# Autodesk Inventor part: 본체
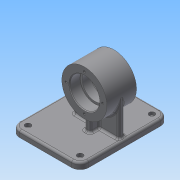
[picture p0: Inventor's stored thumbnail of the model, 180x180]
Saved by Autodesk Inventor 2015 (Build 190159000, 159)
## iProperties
Created: 2019-09
Part Number: 본체
Material: 일반
Document SubType Name: Modeling
Designer: user
Density: 1 g/cm^3
Appearance: 기본값
Author: user
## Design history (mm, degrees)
sketch "스케치1"
  geometry: C1 r 32 at (0, 0); 1 further point
  constraints: 1 centre point, 1 coincident
  dimensions: "d0" = 64 diameter of C1
extrude "돌출1" new body sketch "스케치1" stored distance "d1" = 42; taper "d2" = 0 deg
sketch "스케치2"
  geometry: L1 (32, -21)-(-32, -21) reference; L2 (-32, -21)-(-32, 21) reference; L3 (-32, 21)-(32, 21) reference; L4 (32, 21)-(32, -21) reference; L5 (0, 21)-(0, -21); L6 (21, 21)-(21, 6); L7 (21, 6)-(18, 6); L8 (18, 6)-(18, -6); L9 (18, -6)-(21, -6); L10 (21, -6)-(21, -21); 1 further point
  constraints: 12 end point, 4 point on line, 3 perpendicular, 2 midpoint, 1 vertical
  dimensions: "d3" = 15 distance of L6.start L6.end (= d6); "d4" = 36 diameter of L8 L5; "d5" = 42 diameter of L10 L5; "d6" = 15 distance of L9.end L10.end
revolve "회전1" sketch "스케치2" stored, may be unused: angle "d7" = 90 deg
chamfer "모따기1" distance "d8" = 1; stored, may be unused: second distance "d9" = 2, angle "d10" = 45 deg
fillet "모깎기1" dims "d11" = 0.3
sketch "스케치3"
  geometry: C1 r 32 at (0, 0) reference; 1 further point
  constraints: 1 vertical alignment
  dimensions: "d12" = 26 distance of point (0, 26) C1.centre
hole "구멍1" sketch "스케치3" at (0, 26) diameter "d13" = 3.242; stored, may be unused: countersink angle "d17" = 90 deg, drill point angle "d19" = 118 deg; dims "d14" = 8, "d15" = 4, "d16" = 2, "d18" = 10
node "작업축1"
  node "작업 평면1"
  node "작업 평면2"
sketch "스케치4"
  geometry: L1 (-36, 29.4)-(-36, -29.4) reference; L2 (62, 63)-(-36, 63); L3 (-36, 63)-(-36, -63); L4 (-36, -63)-(62, -63); L5 (62, -63)-(62, 63); L6 (62, 63)-(-36, -63); L7 (-36, 63)-(62, -63); 3 further points
  constraints: 12 end point, 3 midpoint, 2 parallel, 1 horizontal, 1 horizontal alignment, 1 perpendicular, 1 point on line
  dimensions: "d25" = 126 distance of L4.end L2.start; "d26" = 98 distance of L2.start L2.end
extrude "돌출2" join sketch "스케치4" distance "d27" = 9; taper "d28" = 0 deg
fillet "모깎기2" dims "d29" = 12
fillet "모깎기3" dims "d30" = 3
sketch "스케치5"
  geometry: L1 (-50, -51)-(24, -51); L2 (24, -51)-(24, 51); L3 (24, 51)-(-50, 51); L4 (-50, 51)-(-50, -51); A1 r 9 centre (-50, -51) between (-59, -51) and (-50, -60) reference; A2 r 9 centre (24, 51) between (33, 51) and (24, 60) reference; 5 further points
  constraints: 8 end point, 4 coincident, 2 parallel, 1 horizontal, 1 perpendicular
hole "구멍2" sketch "스케치5" at (-50, -51), (24, -51), (24, 51), (-50, 51) diameter "d31" = 4.5; stored, may be unused: countersink angle "d35" = 90 deg, drill point angle "d37" = 0 deg; dims "d32" = 8, "d33" = 8, "d34" = 4.4, "d36" = 10
sketch "스케치6"
  geometry: L1 (4, -17)-(-4, -17); L2 (-4, -17)-(-4, 17); L3 (-4, 17)-(4, 17); L4 (4, 17)-(4, -17); L5 (4, -17)-(-4, 17); L6 (-4, -17)-(4, 17); 1 further point
  constraints: 12 end point, 2 midpoint, 2 parallel, 1 horizontal, 1 perpendicular
  dimensions: "d38" = 8 distance of L2.end L3.end; "d39" = 34 distance of L1.end L2.end
extrude "돌출3" join sketch "스케치6" stored distance "d40" = 9; taper "d41" = 0 deg
sketch "스케치7"
  geometry: L1 (32, -4)-(-32, -4); L2 (-32, -4)-(-32, 4); L3 (-32, 4)-(32, 4); L4 (32, 4)-(32, -4); L5 (32, -4)-(-32, 4); L6 (-32, -4)-(32, 4); 1 further point
  constraints: 12 end point, 2 midpoint, 2 parallel, 1 horizontal, 1 perpendicular
  dimensions: "d42" = 8 distance of L1.end L2.end; "d43" = 32 distance from line of L4 point (0, 0)
extrude "돌출4" join sketch "스케치7" stored distance "d44" = 10; taper "d45" = 0 deg
sketch "스케치8"
  geometry: C1 r 18 at (0, 0) reference; C2 r 18 at (0, 0) reference
extrude "돌출5" cut sketch "스케치8" stored distance "d46" = 20; taper "d47" = 0 deg
fillet "모깎기4" dims "d48" = 3
fillet "모깎기5" dims "d49" = 3
fillet "모깎기6" dims "d50" = 3
node "솔리드1"
pattern_circular "원형 패턴1" dims angle "d21" = 360 deg
mirror "대칭1"
node "투영된 루프1"
node "절단 모서리 투영1"
other parameters: "d23" = -59, "d24" = 36
